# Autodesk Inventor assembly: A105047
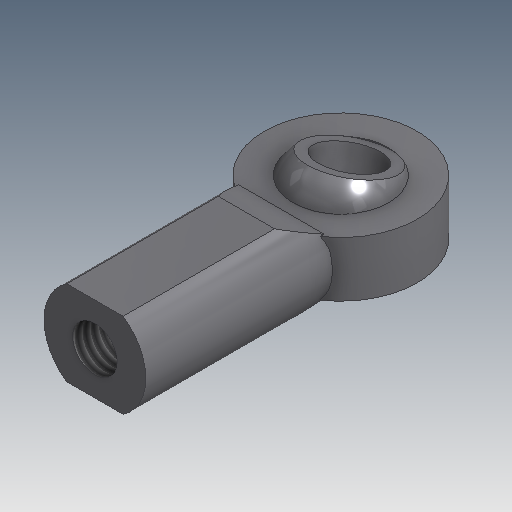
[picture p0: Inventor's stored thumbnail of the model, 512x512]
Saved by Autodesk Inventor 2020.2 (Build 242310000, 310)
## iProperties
Created: 2000-01
Part Number: A105047
Document SubType Name: Assembly
Designer: sspink
Mass: 102.417 g
Surface Area: 67.2258 cm^2
Volume: 13.0634 cm^3
Density: 7.84 g/cm^3
Control State: 0
Checked Out: False
Master: False
Shininess: 0.0
Length Units: 11269
Angle Units: 11279
Time Units: 11290
Mass Units: 11283
Length Display Precision: 3
Angle Display Precision: 2
Compacted: True
Dimensions: 19,8x60,3x28,6 mm
Mass: 0,102 kg
DocNumber: A105047.iam
Folder: 01 - Themengebiete\Simplification\01 - Packaging machine\
VDS_Category: 3D Komponenten
Density: 0.0
Volumn: 0.0
Area: 0.0
PropertySet Name: Model Information
Author: sspink
Revision Number: -
Title: A105047
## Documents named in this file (3)
- D:\07 - DEMODATEN\OTX 2019 - Dataset - UPDATE - Dez2019\Designs\07-Packing machine\A105047.iam
- D:\07 - DEMODATEN\OTX 2019 - Dataset - UPDATE - Dez2019\Designs\07-Packing machine\Parts\ADSK-011787.ipt
- D:\07 - DEMODATEN\OTX 2019 - Dataset - UPDATE - Dez2019\Designs\07-Packing machine\Parts\ADSK-011786.ipt
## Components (2 placed, 2 different names)
1. ADSK-011787:1 — Passend:1
2. ADSK-011786:1 — Passend:1
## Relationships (1: Mate 1)
- Passend:1 [Mate]: ADSK-011787:1 ↔ ADSK-011786:1
